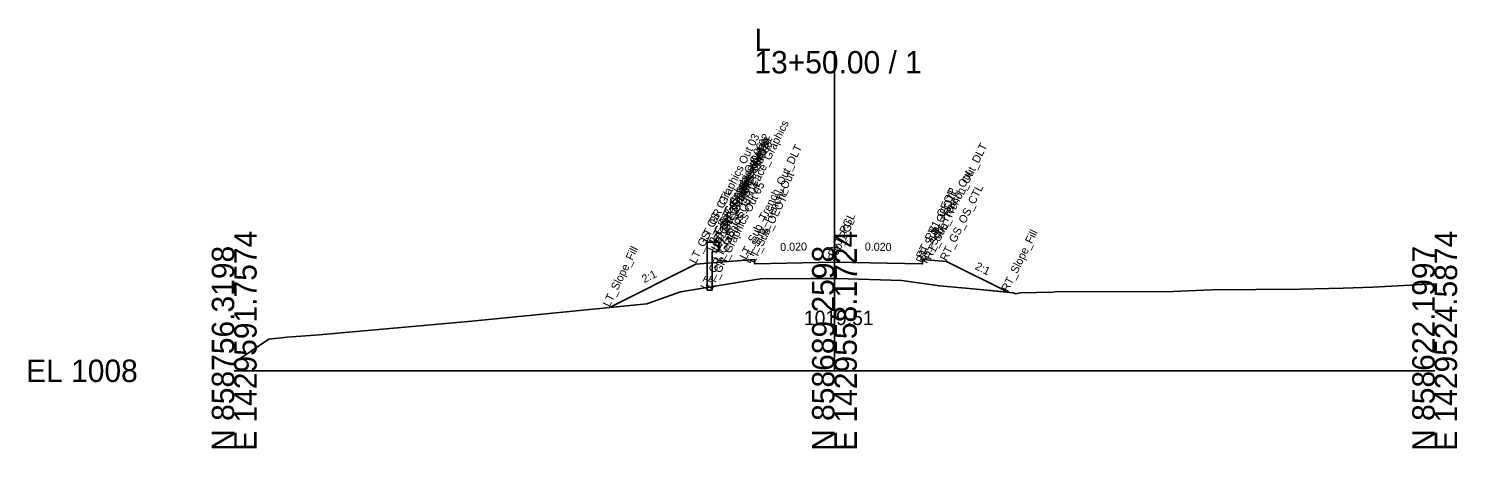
# Model space of a CAD drawing. Extents: x -26 to 176, y -10 to 13058.
# Drawn here: x -25.7 to 152.8, y 3990.3 to 4042.7 of the extents above; entities that cross this region are included whole.
import ezdxf

# ---------------------------------------------------------------- set-up
doc = ezdxf.new("R2010")
doc.units = 0
for name, color, linetype in [('Default', 7, 'Continuous'), ('Exist Cross Section Cell', 7, 'Continuous'), ('Exist XS Center Line Elevation Label', 7, 'Continuous'), ('Exist XS Ground Line', 7, 'Continuous'), ('Old_Level_50', 7, 'Continuous'), ('Prop CMT Guardrail Graphics', 7, 'Continuous'), ('Prop CMT Pvmt Course 1', 7, 'Continuous'), ('Prop CMT Pvmt Surface Shoulder', 7, 'Continuous'), ('Prop CMT Shld Paved Course 1', 7, 'Continuous'), ('Prop CMT Slope Grass', 7, 'Continuous'), ('Prop CMT Subgrade Earthwork', 7, 'Continuous'), ('Prop XS Dump Level', 7, 'Continuous'), ('Prop XS SE Text', 7, 'Continuous'), ('Prop XS Side Slope Text', 7, 'Continuous')]:
    doc.layers.add(name, color=color, linetype=linetype)

msp = doc.modelspace()

# ---------------------------------------------------------------- linework, layer by layer
at = {"layer": 'Exist Cross Section Cell'}
for p, q in [((75, 4000), (75, 4039.93)), ((0, 4000), (75, 4000)), ((75, 4000), (150, 4000))]:
    msp.add_line(p, q, dxfattribs=at)
at = {"layer": 'Exist XS Ground Line'}
msp.add_lwpolyline([(0, 4001.03), (4.32, 4003.94), (6.62, 4004.19), (10.62, 4004.49), (29.71, 4006.2), (51.57, 4008.38), (55.75, 4009.87), (63.39, 4011.1), (65.78, 4011.47), (72.01, 4011.51), (74.2, 4011.52), (75, 4011.51), (76.73, 4011.49), (83.44, 4011.29), (88.12, 4010.63), (90.9, 4010.38), (93.17, 4010.15), (97.32, 4009.74), (97.62, 4009.61), (98.19, 4009.73), (102.31, 4009.81), (102.72, 4009.92), (116.38, 4009.86), (122.13, 4010.13), (133.17, 4010.2), (138.57, 4010.3), (142.28, 4010.46), (150, 4010.86)], dxfattribs=at)
at = {"layer": 'Old_Level_50'}
for points in [[(89.01, 4013.64), (96.69, 4009.8), (93.17, 4010.15), (90.9, 4010.38), (88.12, 4010.63), (83.44, 4011.29), (76.73, 4011.49), (75, 4011.51), (74.2, 4011.52), (72.01, 4011.51), (65.78, 4011.47), (63.39, 4011.1), (55.75, 4009.87), (51.57, 4008.38), (46.88, 4007.91), (57.68, 4013.31), (60.68, 4013.55), (65, 4013.9), (65, 4013.36), (75, 4013.56), (86.01, 4013.34), (86.01, 4013.88)], [(75, 4013.56), (65, 4013.36), (65, 4013.9), (60.68, 4013.55), (57.68, 4013.31), (46.88, 4007.91), (51.57, 4008.38), (55.75, 4009.87), (63.39, 4011.1), (65.78, 4011.47), (72.01, 4011.51), (74.2, 4011.52), (75, 4011.51), (76.73, 4011.49), (83.44, 4011.29), (88.12, 4010.63), (90.9, 4010.38), (93.17, 4010.15), (96.69, 4009.8), (89.01, 4013.64), (86.01, 4013.88), (86.01, 4013.34)], [(75, 4013.56), (65, 4013.36), (65, 4013.9), (60.68, 4013.55), (57.68, 4013.31), (46.88, 4007.91), (51.57, 4008.38), (55.75, 4009.87), (63.39, 4011.1), (65.78, 4011.47), (72.01, 4011.51), (74.2, 4011.52), (75, 4011.51), (76.73, 4011.49), (83.44, 4011.29), (88.12, 4010.63), (90.9, 4010.38), (93.17, 4010.15), (96.69, 4009.8), (89.01, 4013.64), (86.01, 4013.88), (86.01, 4013.34)]]:
    msp.add_lwpolyline(points, close=True, dxfattribs=at)
at = {"layer": 'Prop CMT Guardrail Graphics'}
for points in [[(59.08, 4010.05), (59.08, 4016.05)], [(59.08, 4016.05), (60.41, 4016.05), (60.68, 4015.76)], [(60.68, 4015.76), (60.41, 4015.47)], [(60.41, 4015.47), (60.68, 4015.18)], [(60.68, 4015.18), (60.41, 4014.88), (59.74, 4014.88)], [(59.74, 4014.88), (59.74, 4010.05)], [(59.74, 4010.05), (59.08, 4010.05)]]:
    msp.add_lwpolyline(points, dxfattribs=at)
at = {"layer": 'Prop CMT Pvmt Course 1'}
for points in [[(65, 4013.9), (65, 4013.36)], [(65, 4013.36), (75, 4013.56)], [(86.01, 4013.34), (75, 4013.56)], [(86.01, 4013.88), (86.01, 4013.34)]]:
    msp.add_lwpolyline(points, dxfattribs=at)
at = {"layer": 'Prop CMT Pvmt Surface Shoulder'}
for points in [[(65, 4013.9), (65, 4013.9)], [(86.01, 4013.88), (86.01, 4013.88)]]:
    msp.add_lwpolyline(points, dxfattribs=at)
at = {"layer": 'Prop CMT Shld Paved Course 1'}
for points in [[(65, 4013.9), (65, 4013.9)], [(65, 4013.36), (65, 4013.9)], [(86.01, 4013.88), (86.01, 4013.88)], [(86.01, 4013.34), (86.01, 4013.88)]]:
    msp.add_lwpolyline(points, dxfattribs=at)
at = {"layer": 'Prop CMT Slope Grass'}
for points in [[(60.68, 4013.55), (57.68, 4013.31)], [(65, 4013.9), (60.68, 4013.55)], [(86.01, 4013.88), (89.01, 4013.64), (96.69, 4009.8)], [(57.68, 4013.31), (46.88, 4007.91)]]:
    msp.add_lwpolyline(points, dxfattribs=at)
at = {"layer": 'Prop CMT Subgrade Earthwork'}
for points in [[(75, 4013.56), (65, 4013.36)], [(75, 4013.56), (86.01, 4013.34)]]:
    msp.add_lwpolyline(points, dxfattribs=at)

# ---------------------------------------------------------------- texts
at = {"layer": 'Default'}
msp.add_text('-', height=0.0001, dxfattribs=at).set_placement((0, 4000))
at = {"layer": 'Exist Cross Section Cell'}
for s, p in [('L', (65, 4039.93)), ('13+50.00 / 1', (65, 4037.13)), ('EL 1008', (-26, 3998.6))]:
    msp.add_text(s, height=2.8, dxfattribs=at).set_placement(p)
for s, p in [('E 1429591.7574', (2.8, 3990)), ('E 1429558.1724', (77.8, 3990)), ('E 1429524.5874', (152.8, 3990)), ('N 858756.3198', (0, 3990)), ('N 858689.2598', (75, 3990)), ('N 858622.1997', (150, 3990))]:
    msp.add_text(s, height=2.8, rotation=90, dxfattribs=at).set_placement(p)
at = {"layer": 'Exist XS Center Line Elevation Label'}
msp.add_text('1019.51', height=1.8, dxfattribs=at).set_placement((71.19, 4005.71))
msp.add_text('1019.51', height=1.8, dxfattribs=at).set_placement((71.19, 4005.71))
msp.add_text('1019.51', height=1.8, dxfattribs=at).set_placement((71.19, 4005.71))
at = {"layer": 'Prop XS Dump Level'}
for s, p in [('LT_GR_Graphics Out 03', (59.08, 4016.05)), ('LT_GR_Graphics Out 02', (60.41, 4016.05)), ('LT_GS_OS_GR_Face_Graphics', (60.68, 4013.55)), ('LT_GR_Graphics Out 06', (59.74, 4014.88)), ('LT_GR_Graphics Out 09', (60.41, 4015.47)), ('LT_GR_Graphics Out 07', (60.41, 4014.88)), ('LT_GR_Graphics Out 01', (60.68, 4015.76)), ('LT_GR_Graphics Out 08', (60.68, 4015.18)), ('LT_Sub_Trench_Out_DLT', (63.98, 4013.82)), ('RT_Sub_Trench_Out_DLT', (87.03, 4013.79)), ('LT_Sub_Trench_Out', (64.45, 4013.34)), ('RT_Sub_Trench_Out', (86.56, 4013.32)), ('LT_GS_OS_CTL', (57.68, 4013.31)), ('LT_GR_Graphics Out 04', (59.08, 4010.05)), ('LT_GR_Graphics Out 05', (59.74, 4010.05)), ('LT_PV1_OEOT', (65, 4013.9)), ('LT_PS1_OEOP', (65, 4013.9)), ('RT_PV1_OEOT', (86.01, 4013.88)), ('RT_PS1_OEOP', (86.01, 4013.88)), ('RT_GS_OS_CTL', (89.01, 4013.64)), ('RT_GS_OS_CTL', (89.01, 4013.64)), ('LT_Sub_OEOT', (65, 4013.36)), ('RT_Sub_OEOT', (86.01, 4013.34)), ('PV1_PGL', (75, 4014.1)), ('Sub_PGL', (75, 4013.56)), ('RT_Slope_Fill', (96.69, 4009.8)), ('RT_Slope_Fill', (96.69, 4009.8)), ('LT_Slope_Fill', (46.88, 4007.91))]:
    msp.add_text(s, height=1, rotation=63.5833, dxfattribs=at).set_placement(p)
at = {"layer": 'Prop XS SE Text'}
for rotation, p in [(1.1458, (68.23, 4014.96)), (358.8542, (78.78, 4015.02))]:
    msp.add_text('0.020', height=1, rotation=rotation, dxfattribs=at).set_placement(p)
at = {"layer": 'Prop XS Side Slope Text'}
for rotation, p in [(333.4349, (92.48, 4012.74)), (26.5651, (51.24, 4010.93))]:
    msp.add_text('2:1', height=1, rotation=rotation, dxfattribs=at).set_placement(p)

doc.saveas('drawing.dxf')
